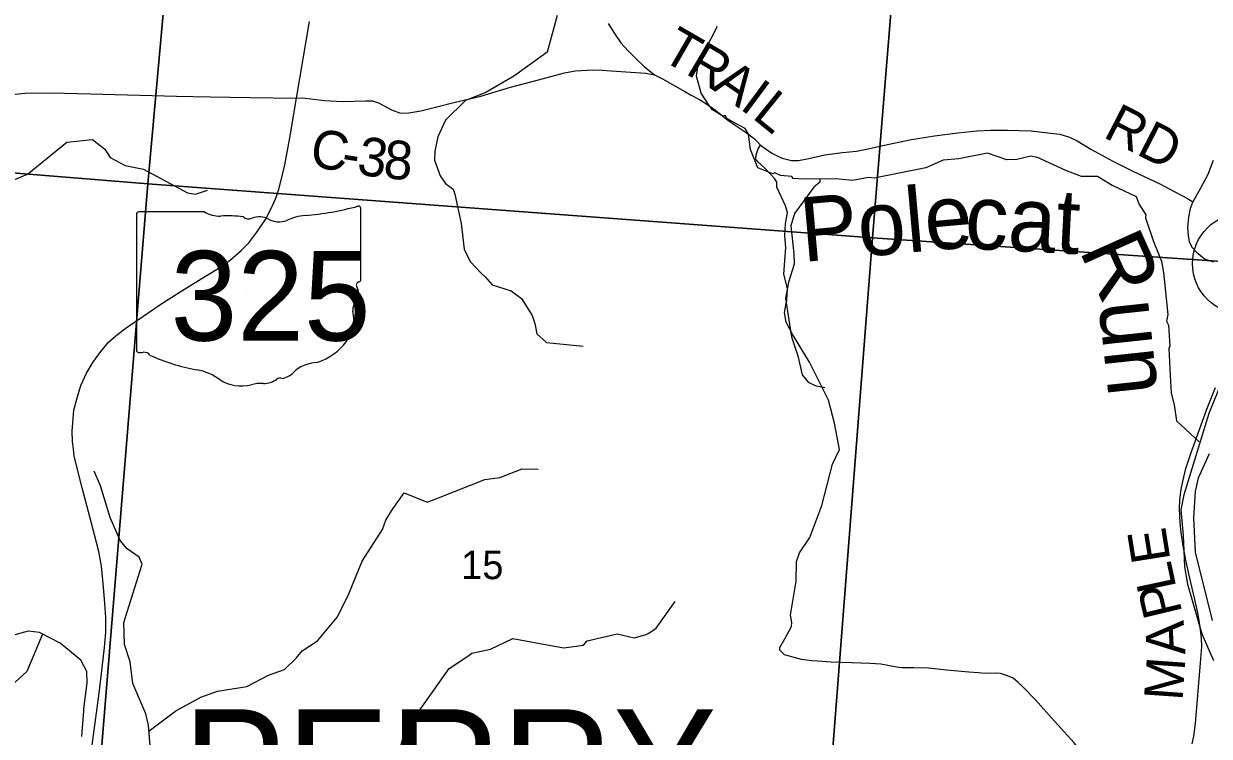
# Model space of a CAD drawing. Extents: x 1878108 to 2183446, y 146837 to 508383.
# Drawn here: x 1996150 to 2005354, y 296632 to 302166 of the extents above; entities that cross this region are included whole.
import ezdxf

# ---------------------------------------------------------------- set-up
doc = ezdxf.new("R2010")
doc.units = 0
for name, color, linetype in [('GM_X_County_Road', 7, 'Continuous'), ('GM_X_County_Road_Text', 7, 'Continuous'), ('GM_X_Major_River', 7, 'Continuous'), ('GM_X_Minor_River', 7, 'Continuous'), ('GM_X_Minor_River_Text', 7, 'Continuous'), ('GM_X_Section', 7, 'Continuous'), ('GM_X_Section_Text', 7, 'Continuous'), ('GM_X_State_Location', 7, 'Continuous'), ('GM_X_State_Route', 7, 'Continuous'), ('GM_X_State_Shield', 7, 'Continuous'), ('GM_X_Township_Road', 7, 'Continuous'), ('GM_X_Township_ROW', 7, 'Continuous'), ('GM_X_Township_Text', 7, 'Continuous'), ('GM_X_Unincorporated', 7, 'Continuous')]:
    doc.layers.add(name, color=color, linetype=linetype)

msp = doc.modelspace()

# ---------------------------------------------------------------- linework, layer by layer
at = {"layer": 'GM_X_County_Road'}
for points in [[(2000687.3, 302167.8), (2000736, 302089.6), (2000786, 302016.5), (2000841.2, 301958.8), (2000901.4, 301897.2), (2000966.8, 301834.4), (2001047.6, 301769), (2001110.4, 301737), (2001187.4, 301694.6), (2001282.3, 301639.5), (2001326.5, 301615), (2001391.3, 301579.2), (2001450.3, 301543.3), (2001513.1, 301499.7), (2001614.4, 301420.2), (2001674.7, 301379.2), (2001750.3, 301326.6), (2001823.4, 301272.8), (2001845.2, 301251), (2001869.6, 301224), (2001956.8, 301161.2), (2001994, 301142), (2002037.6, 301122.7), (2002110.7, 301103.5), (2002164.5, 301104.8), (2002245.3, 301118.9), (2002369.7, 301147.1), (2002505.6, 301165), (2002614.6, 301175.6), (2002681.3, 301188.1), (2002832.6, 301222.7), (2003026.2, 301265.1), (2003219.9, 301295.8), (2003403.3, 301317.6), (2003550.7, 301334.3), (2003654.6, 301339.4), (2003786.7, 301338.2), (2003971.3, 301333), (2004100.8, 301317.6), (2004193.2, 301307.4), (2004268.8, 301285.6), (2004329.1, 301256.1), (2004434.2, 301192), (2004604.8, 301099.6), (2004760, 301021.4), (2004970.3, 300921.4), (2005047.2, 300880.4), (2005184.4, 300808.6), (2005225.4, 300781.6)], [(1998269.1, 301586.8), (1998313.8, 301589.5), (1998484.9, 301569.6), (1998625.5, 301562), (1998804.3, 301566.6), (1998857.7, 301568.1), (1998905.1, 301552.8), (1999005.9, 301497.8), (1999076.2, 301471.9), (1999138.8, 301473.4), (1999233.1, 301489.5), (1999347.2, 301519), (1999488.3, 301553.6), (1999698.6, 301603.6), (1999929.4, 301672.8), (2000147.4, 301730.5), (2000348.7, 301784.4), (2000432.1, 301799.8), (2000566.7, 301807.5), (2000639.8, 301804.9), (2000825.8, 301793.4), (2000980.9, 301783.1), (2001047.6, 301769)], [(1996034.2, 301613.5), (1996161.7, 301626.8), (1996366.4, 301629.8), (1996668.9, 301620.9), (1997147.9, 301607.6), (1997336.3, 301604.6), (1997598.8, 301597.2), (1997908.8, 301592.7), (1998269.1, 301586.8)], [(2005384.5, 301103.5), (2005343.4, 300995.8), (2005284.4, 300882.9), (2005225.4, 300781.6), (2005204.9, 300731.6), (2005193.4, 300664.9), (2005185.7, 300582.9), (2005190.8, 300518.7), (2005197.2, 300473.9), (2005219, 300430.3), (2005258.8, 300386.7), (2005322.9, 300337.9), (2005385.7, 300316.1)], [(2005220.3, 296573.3), (2005234.6, 296632.9), (2005247.8, 296730.7), (2005287.1, 297203.1), (2005295.5, 297327.1), (2005294.3, 297396.3), (2005280, 297498.9), (2005266.8, 297577.6), (2005243, 297694.5), (2005210.8, 297826.8), (2005173.8, 297986.7), (2005152.3, 298111.9), (2005135.6, 298214.5), (2005127.3, 298289.6), (2005123.7, 298401.7), (2005126.1, 298467.3), (2005135.6, 298548.4), (2005148.8, 298611.7), (2005173.1, 298712.9), (2005214.4, 298837.1), (2005277.6, 299016), (2005336, 299173.4), (2005401.6, 299341.6)]]:
    msp.add_lwpolyline(points, dxfattribs=at)
at = {"layer": 'GM_X_Major_River'}
for points in [[(2005451.3, 299388.6), (2005350, 299137.8), (2005155.8, 298508), (2005134.1, 298389.8), (2005150.7, 298191.5), (2005152.8, 298133.4), (2005161.4, 297947.1), (2005183.8, 297813), (2005296.9, 297426.7), (2005387.5, 297220.7)], [(2005378.6, 297531.2), (2005247, 298061.6), (2005234.3, 298330), (2005247.7, 298532.4), (2005271.4, 298638.7), (2005354.9, 298827.3)]]:
    msp.add_lwpolyline(points, dxfattribs=at)
at = {"layer": 'GM_X_Minor_River'}
for points in [[(2000292.8, 302230.6), (2000213, 301944.5), (1999971.9, 301767.8), (1999942.6, 301749.7), (1999737.6, 301631), (1999578.7, 301569.4), (1999423.6, 301417.1), (1999364.5, 301286.4), (1999342.9, 301177.2), (1999340.1, 301107), (1999384.1, 300985.4), (1999424.2, 300926.4), (1999483.3, 300880.1), (1999496.9, 300843), (1999547.5, 300614.3), (1999570.1, 300415.7), (1999615.8, 300320.1), (1999705.6, 300223.4), (1999732.2, 300201.5), (1999786.1, 300137.5), (1999933.6, 300091.3), (2000015.8, 300031.4), (2000097.3, 299901.1), (2000119.1, 299837.3), (2000133.7, 299757.9), (2000207.5, 299690.5), (2000492.9, 299663)], [(2004012.7, 301128.3), (2003967.5, 301138.6), (2003859.5, 301112.4), (2003783.4, 301108.3), (2003631.2, 301162), (2003409.1, 301115.6), (2003287, 301105.4), (2003153.1, 301047.1), (2002907, 300996.7), (2002753, 300966.4), (2002709, 300972.3), (2002584.9, 300948.1), (2002452.8, 300961.9), (2002204.6, 300959.4), (2002122.5, 300963.3), (2002114.5, 300979.3), (2002024.4, 300987.1), (2001982.3, 301009), (2001966.3, 301001), (2001850.1, 301046.8), (2001791.6, 301188.7), (2001777.3, 301308.7), (2001751.1, 301352.6), (2001701, 301378.6), (2001608.8, 301430.4), (2001594.7, 301454.4), (2001578.7, 301448.3), (2001496.5, 301498.2), (2001470.4, 301532.1), (2001410.1, 301626), (2001373.7, 301760), (2001385.5, 301848), (2001393.4, 301870), (2001532.8, 302142.3), (2001528.8, 302146.3)], [(1996000.2, 300865.4), (1996050.6, 300943.1), (1996180.8, 300996.6), (1996402.2, 301178.6), (1996485.1, 301245.3), (1996685.4, 301265.9), (1996778.8, 301193.1), (1996820.4, 301126), (1996938.8, 301065.6), (1997081.4, 301035.8), (1997422.4, 300851.6), (1997484.1, 300843.4), (1997575.9, 300872.5)], [(2004012.7, 301132.4), (2004237.5, 301029.5), (2004360.4, 300982.5), (2004486.6, 300981.6), (2004599.8, 300912.5), (2004785.4, 300824), (2004806.2, 300766), (2004861.4, 300682.3), (2004857.7, 300658.3), (2004922.3, 300474.5), (2004984.4, 300322.7), (2004997.6, 300234.7), (2005031.9, 299908.3), (2005022.6, 299856.1), (2005037.1, 299824.2), (2005047.2, 299662), (2005039.4, 299643.9), (2005050.2, 299437.5), (2005058, 299297.3), (2005081.3, 299205.4), (2005100.9, 299083.3), (2005275.9, 298919.5)], [(2002330.6, 300960.7), (2002330.8, 300935.6), (2002284.8, 300897.6), (2002207.1, 300789.4), (2002133.3, 300693.3), (2002105.5, 300597.2), (2002130.1, 300379.3), (2002132.4, 300299.3), (2002088.7, 300159.2), (2002063, 300035.1), (2002079.3, 299931.2), (2002111.9, 299733.2), (2002160.4, 299587.3), (2002194.8, 299439.4), (2002241, 299383.5), (2002295.1, 299355.5), (2002305.1, 299353.5), (2002369.2, 299339.7)], [(1997019, 296353.4), (1997134.7, 296527.8), (1997119.5, 296717.8), (1997097.4, 296805.8), (1996997.1, 297041.8), (1996976.5, 297210.1), (1996933.5, 297345.8), (1996927.1, 297517.1), (1997068.5, 297968), (1997046.2, 298023.8), (1996954.2, 298088.4), (1996898.3, 298152.5), (1996822.2, 298332.6), (1996746.5, 298577.1), (1996696.1, 298691.1)], [(1997124.5, 296673.4), (1997332.1, 296830), (1997526.3, 296937.4), (1997655.9, 296982.9), (1997881.4, 297019.8), (1998050.1, 297106.8), (1998173.6, 297150.7), (1998268.3, 297242.8), (1998312.1, 297296.1), (1998429.9, 297372.5), (1998587.4, 297560.8), (1998673.8, 297737.9), (1998777.6, 297992.3), (1998935.1, 298238.9), (1998962, 298309.5), (1999005.2, 298382.9), (1999103.2, 298523), (1999283, 298450.5), (1999382.1, 298490), (1999728.8, 298625.2), (1999846.6, 298643.3), (2000019.9, 298709.9), (2000140.3, 298707.8), (2000141.4, 298703.7)], [(1999387.5, 294943.5), (1999392.6, 295324.3), (1999325.5, 295517.9), (1999105, 296200.5), (1999068.6, 296373.9), (1999064.5, 296518.9), (1999118, 296684.2), (1999215.8, 296822.3), (1999453.7, 297158), (1999598.9, 297254.6), (1999628.7, 297278.8), (1999773.4, 297309.1), (1999947.8, 297391.7), (2000213.7, 297343.4), (2000342.5, 297318.6), (2000496.7, 297340.2), (2000525.2, 297374.5), (2000757.7, 297427), (2000888.3, 297398), (2000974.2, 297420.3), (2001003.2, 297432.4), (2001060, 297470.8), (2001208.8, 297677.8)], [(1996600.3, 296629.4), (1996615.7, 296829.4), (1996615.7, 296845.4), (1996643.1, 297047.5), (1996640.9, 297135.5), (1996592.6, 297223.4), (1996520.4, 297283.2), (1996432.1, 297355.1), (1996271.8, 297438.8), (1996185.7, 297448.6), (1996053.7, 297412.4)], [(1996295.5, 297426.4), (1996173.9, 297136.1), (1996055.9, 297025.5)]]:
    msp.add_lwpolyline(points, dxfattribs=at)
at = {"layer": 'GM_X_Section'}
for points in [[(1997595.1, 306264.2), (1997112.9, 300922.7), (1991629.4, 301366.7), (1992093.7, 306704.1)], [(1997595.1, 306264.2), (2003174.6, 305842.2), (2002740.4, 300502.8), (1997112.9, 300922.7)], [(2008621.5, 305451.6), (2008238.6, 300131.7), (2002740.4, 300502.8), (2003174.6, 305842.2)], [(1997112.9, 300922.7), (1996672.7, 295553.3), (1991165.2, 296023.3), (1991629.4, 301366.7)], [(2002740.4, 300502.8), (2002320.3, 295109.3), (1996672.7, 295553.3), (1997112.9, 300922.7)], [(2008238.6, 300131.7), (2007847.8, 294715.6), (2002320.3, 295109.3), (2002740.4, 300502.8)]]:
    msp.add_lwpolyline(points, close=True, dxfattribs=at)
at = {"layer": 'GM_X_State_Route'}
msp.add_lwpolyline([(1996671.8, 296487.5), (1996734.7, 296966.3), (1996759, 297164.9), (1996777.6, 297320.7), (1996787.6, 297440.7), (1996787.6, 297553.6), (1996780.4, 297663.7), (1996770.4, 297790.9), (1996753.3, 297952.4), (1996733.3, 298068.1), (1996677.5, 298286.8), (1996604.6, 298562.6), (1996541.8, 298807), (1996536, 298864.1), (1996528.9, 298922.7), (1996527.5, 299002.8), (1996530.3, 299067.1), (1996540.3, 299165.7), (1996564.6, 299261.4), (1996594.6, 299355.8), (1996637.5, 299451.5), (1996687.5, 299535.8), (1996749, 299620.1), (1996811.9, 299694.5), (1996881.9, 299754.1), (1996944.8, 299804.5), (1997074.8, 299893.1), (1997207.7, 299981.7), (1997364.9, 300083.2), (1997560.7, 300206.1), (1997673.6, 300273.3), (1997756.5, 300333.3), (1997839.4, 300404.7), (1997896.6, 300464.8), (1997959.4, 300547.6), (1998028, 300646.3), (1998070.8, 300730.5), (1998106.6, 300810.6), (1998129.5, 300880.6), (1998152.4, 300960.7), (1998176.7, 301070.7), (1998216.7, 301280.8), (1998269.1, 301586.8), (1998370, 302183)], dxfattribs=at)
at = {"layer": 'GM_X_State_Shield'}
for p, q in [((1997553.3, 300705.4), (1997043.6, 300705.4)), ((1998766.7, 300178.8), (1998766.7, 300731.6)), ((1997026.5, 300687.2), (1997026.5, 299630.6)), ((1998766.5, 300178.9), (1998766.7, 300178.8))]:
    msp.add_line(p, q, dxfattribs=at)
for centre, major_axis, start_param, end_param in [((1997046.4, 300689.4), (20.2, 0), 1.712693, 3.28349), ((1997674.6, 300828), (195.5, 0), 4.042523, 4.731795), ((1998146.8, 302145.9), (1845.5, 0), 4.814394, 5.042369), ((1998747.4, 300733.8), (19.4, 0), 6.141152, 7.989035), ((1997739.5, 300112.2), (702, 0), 1.404758, 1.657858), ((1997898.8, 300694.9), (56.4, 0), 3.836095, 5.185415), ((1997981.7, 300572.8), (117.3, 0), 0.950623, 2.079405), ((1998133, 300740.3), (141.1, 0), 4.081561, 5.145723), ((1998382.2, 300382.6), (371.3, 0), 1.699011, 2.107814), ((1998762.2, 300138.2), (30, 0), 1.883978, 3.671073), ((1998746, 300176.7), (20.7, 0), 5.05454, 6.418171), ((1998571.5, 300068.4), (180, 0), 5.934695, 6.695948), ((1998836.1, 299947.5), (130.9, 0), 2.387724, 3.262537), ((1998250.2, 299877.2), (461.6, 0), 5.101752, 6.440018), ((1997046.6, 299628.2), (20.3, 0), 3.00124, 4.508301), ((1997049.7, 299736.3), (155.2, 0), 4.665946, 4.897461), ((1997081.5, 299569.6), (56, 0), 0.519207, 1.627899), ((1997788.1, 300518.9), (1332.7, 0), 4.195997, 4.488961), ((1998444.8, 299333.9), (252.8, 0), 1.647645, 2.488434), ((1997390.7, 299155.9), (417, 0), 0.823519, 1.323587), ((1998013.9, 299485.2), (141, 0), 4.691044, 5.507374), ((1998141.5, 299382.9), (39.7, 0), 1.147584, 2.315152), ((1998124.5, 299528.1), (149.1, 0), 4.937069, 5.64225), ((1997841.7, 299564.3), (264.6, 0), 4.026481, 4.996735), ((1997994.6, 299199), (217.4, 0), 1.495662, 1.94098)]:
    msp.add_ellipse(centre, major_axis=major_axis, ratio=0.8, start_param=start_param, end_param=end_param, dxfattribs=at)
at = {"layer": 'GM_X_Township_Road'}
msp.add_lwpolyline([(2004997, 296406.1), (2004977, 296427.8), (2004942.4, 296442.1), (2004845.8, 296439.7), (2004718.2, 296444.5), (2004596, 296453.7), (2004505.9, 296463.6), (2004445.1, 296469.5), (2004405.7, 296479.1), (2004372.3, 296500.6), (2004341.3, 296533.9), (2004304.3, 296580.5), (2004152.8, 296749.8), (2004003.8, 296915.6), (2003906, 297017), (2003871.4, 297050.4), (2003832, 297083.8), (2003786.7, 297102.9), (2003734.2, 297119.6), (2003696, 297123.1), (2003613.7, 297120.8), (2003563.6, 297124.3), (2003488.5, 297130.3), (2003374.4, 297140.4)], dxfattribs=at)
at = {"layer": 'GM_X_Township_ROW'}
msp.add_lwpolyline([(2003374.4, 297140.4), (2003313.2, 297145.8), (2003173.6, 297160.1), (2003060.3, 297163.7), (2002966.1, 297164.9), (2002926.7, 297169.7), (2002858.8, 297182.8), (2002803.9, 297192.3), (2002721.6, 297198.3), (2002576.1, 297201.9), (2002419.8, 297207.8), (2002313.7, 297216.2), (2002268.4, 297218.6), (2002189.6, 297229.3), (2002057.2, 297263.9), (2002019.1, 297302.1), (2002020.8, 297322.4), (2002058.4, 297387.9), (2002109.7, 297484.5), (2002114.5, 297515.5), (2002102.6, 297574), (2002146.7, 297836.4), (2002150.3, 297990.2), (2002172.9, 298055.8), (2002252.9, 298176.3), (2002345.9, 298424.4), (2002429.4, 298746.4), (2002484.2, 298858.5), (2002443.7, 299063.7), (2002398.4, 299242.6), (2002250.5, 299538.4), (2002121.7, 299750.7), (2002069.7, 299847.5), (2002057.2, 299922.4), (2002073.9, 300022.6), (2002078.7, 300108.5), (2002052.5, 300220.6), (2002066.8, 300428.1), (2002059.4, 300518.7), (2002063.2, 300611.1), (2002079.9, 300700.8), (2002062.9, 300752.9), (2001996.5, 300897), (2001995.9, 300934.6), (2001982.4, 300961.1), (2001902.9, 301043.2), (2001848.8, 301094.6), (2001835, 301113.7), (2001836.2, 301148.4), (2001851.6, 301194.5), (2001869.6, 301224)], dxfattribs=at)
at = {"layer": 'GM_X_Unincorporated'}
msp.add_circle((2005617, 300302.9), 392.8, dxfattribs=at)

# ---------------------------------------------------------------- texts
at = {"layer": 'GM_X_County_Road_Text'}
for s, rotation, p in [('T', 329.9447, (2001085.5, 301894.2)), ('R', 329.45728, (2001279.2, 301782.1)), ('A', 325.07826, (2001486.3, 301660.2)), ('I', 323.37287, (2001700.8, 301510.4)), ('L', 320.96872, (2001797.1, 301439)), ('RD', 332.7721, (2004521.2, 301289.7)), ('C', 350.4918, (1998361.5, 301060.4)), ('3', 350.87434, (1998728.3, 300999.5)), ('8', 355.38589, (1998936.4, 300967.1)), ('-', 350.75021, (1998606, 301019.5)), ('E', 99.08961, (2005053.6, 298001.3)), ('L', 102.08279, (2005099.8, 297786)), ('P', 103.44577, (2005146.4, 297591)), ('A', 93.11725, (2005169.3, 297269)), ('M', 85.94131, (2005145.9, 296903.2))]:
    msp.add_text(s, height=300, rotation=rotation, dxfattribs=at).set_placement(p)
at = {"layer": 'GM_X_Minor_River_Text'}
for s, height, rotation, p in [('Pole', 500, 5.10258, (2002199.5, 300315)), ('cat', 500, 357.10271, (2003449.1, 300421.5)), ('R', 500, 294.10515, (2004340.3, 300410.5)), ('un', 499.98, 276.10549, (2004494.2, 299998.5))]:
    msp.add_text(s, height=height, rotation=rotation, dxfattribs=at).set_placement(p)
at = {"layer": 'GM_X_Section_Text'}
msp.add_text('15', height=221, rotation=0.00001, dxfattribs=at).set_placement((1999545.8, 297852.6))
at = {"layer": 'GM_X_State_Location'}
for s in ['s', 'r']:
    msp.add_text(s, height=1, dxfattribs=at).set_placement((1997877, 300088.6))
msp.add_text('325', height=1, rotation=0.00001, dxfattribs=at).set_placement((1997524, 300015.9))
at = {"layer": 'GM_X_State_Shield'}
msp.add_text('325', height=696.1, dxfattribs=at).set_placement((1997290.1, 299705.1))
at = {"layer": 'GM_X_Township_Text'}
msp.add_text('PERRY', height=900, rotation=0.00001, dxfattribs=at).set_placement((1997383.4, 295942))

doc.saveas('drawing.dxf')
